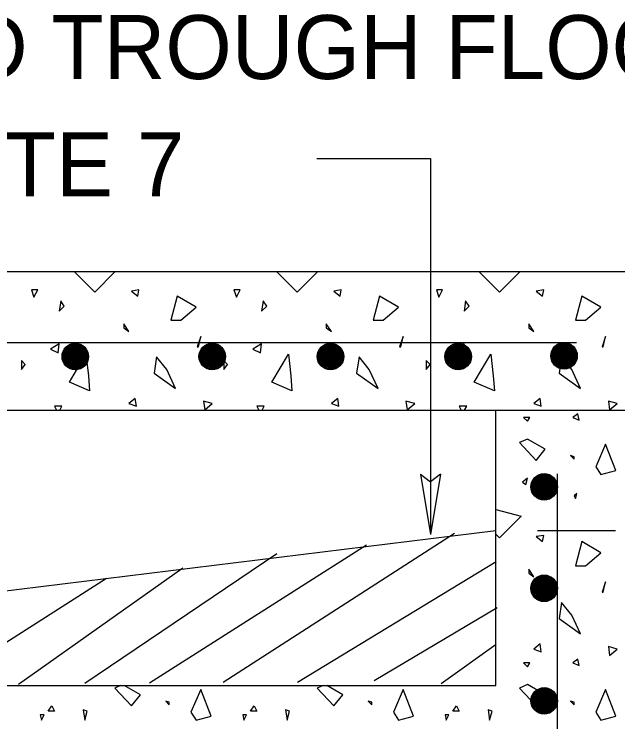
# Model space of a CAD drawing. Extents: x 5.8 to 18, y -5.2 to 5.4.
# Drawn here: x 8.074 to 8.641, y -0.237 to 0.427 of the extents above; entities that cross this region are included whole.
import ezdxf

# ---------------------------------------------------------------- set-up
doc = ezdxf.new("R2010")
doc.units = 0
for name, color, linetype in [('DETL-DIMS', 7, 'Continuous'), ('DETL-LINE', 7, 'Continuous'), ('DETL-NOTE', 7, 'Continuous'), ('DETL-PATT', 7, 'Continuous')]:
    doc.layers.add(name, color=color, linetype=linetype)

msp = doc.modelspace()

# ---------------------------------------------------------------- linework, layer by layer
at = {"layer": 'DETL-DIMS'}
for p, q in [((8.35804, 0.29176), (8.46478, 0.29176)), ((8.46478, 0.29176), (8.46478, -0.06106)), ((8.45537, -0.00459), (8.46478, -0.06106)), ((8.45537, -0.00459), (8.46478, -0.01165)), ((8.4742, -0.00459), (8.46478, -0.06106)), ((8.4742, -0.00459), (8.46478, -0.01165)), ((8.56541, -0.05742), (8.63843, -0.05742))]:
    msp.add_line(p, q, dxfattribs=at)
at = {"layer": 'DETL-LINE'}
for p, q in [((6.26486, 0.18564), (8.65804, 0.18564)), ((7.74588, 0.11902), (8.60188, 0.11902)), ((6.26243, 0.05545), (8.65804, 0.05545)), ((8.5262, -0.20279), (8.5262, 0.05545)), ((8.58404, -0.24561), (8.58404, -0.00424)), ((7.73561, -0.15436), (8.5262, -0.05742)), ((6.404, -0.20279), (8.5262, -0.20279))]:
    msp.add_line(p, q, dxfattribs=at)
for centre, radius in [((8.13138, 0.10591), 0.01247), ((8.13127, 0.10602), 0.01163), ((8.13016, 0.10602), 0.01009), ((8.13141, 0.10572), 0.01122), ((8.13175, 0.10519), 0.011), ((8.13169, 0.10558), 0.01024), ((8.13057, 0.10651), 0.00834), ((8.13196, 0.10552), 0.00969), ((8.13204, 0.10525), 0.00918), ((8.13218, 0.10511), 0.00876), ((8.13204, 0.1049), 0.00835), ((8.13225, 0.1049), 0.00814), ((8.25997, 0.10591), 0.01247), ((8.25986, 0.10602), 0.01163), ((8.25875, 0.10602), 0.01009), ((8.26, 0.10572), 0.01122), ((8.26033, 0.10519), 0.011), ((8.26027, 0.10558), 0.01024), ((8.25916, 0.10651), 0.00834), ((8.26055, 0.10552), 0.00969), ((8.26063, 0.10525), 0.00918), ((8.26076, 0.10511), 0.00876), ((8.26063, 0.1049), 0.00835), ((8.26084, 0.1049), 0.00814), ((8.37103, 0.10591), 0.01247), ((8.37092, 0.10602), 0.01163), ((8.3698, 0.10602), 0.01009), ((8.37106, 0.10572), 0.01122), ((8.37139, 0.10519), 0.011), ((8.37133, 0.10558), 0.01024), ((8.37022, 0.10651), 0.00834), ((8.37161, 0.10552), 0.00969), ((8.37169, 0.10525), 0.00918), ((8.37182, 0.10511), 0.00876), ((8.37169, 0.1049), 0.00835), ((8.3719, 0.1049), 0.00814), ((8.49083, 0.10591), 0.01247), ((8.49073, 0.10602), 0.01163), ((8.48961, 0.10602), 0.01009), ((8.49086, 0.10572), 0.01122), ((8.4912, 0.10519), 0.011), ((8.49114, 0.10558), 0.01024), ((8.49002, 0.10651), 0.00834), ((8.49141, 0.10552), 0.00969), ((8.49149, 0.10525), 0.00918), ((8.49163, 0.10511), 0.00876), ((8.49149, 0.1049), 0.00835), ((8.49171, 0.1049), 0.00814), ((8.5902, 0.10655), 0.01247), ((8.59009, 0.10665), 0.01163), ((8.58897, 0.10665), 0.01009), ((8.59023, 0.10636), 0.01122), ((8.59056, 0.10583), 0.011), ((8.5905, 0.10622), 0.01024), ((8.58938, 0.10714), 0.00834), ((8.59078, 0.10616), 0.00969), ((8.59085, 0.10589), 0.00918), ((8.58919, 0.10616), 0.00724), ((8.59099, 0.10575), 0.00876), ((8.59085, 0.10554), 0.00835), ((8.59107, 0.10554), 0.00814), ((8.59091, 0.10567), 0.00786), ((8.59127, 0.10548), 0.00751), ((8.13037, 0.10552), 0.00724), ((8.12975, 0.10511), 0.00578), ((8.1321, 0.10503), 0.00786), ((8.13245, 0.10484), 0.00751), ((8.13253, 0.10498), 0.00704), ((8.13071, 0.10539), 0.00467), ((8.13259, 0.10505), 0.00655), ((8.13259, 0.10519), 0.006), ((8.13267, 0.10503), 0.00565), ((8.13267, 0.10498), 0.0051), ((8.13288, 0.10454), 0.00488), ((8.133, 0.10449), 0.00445), ((8.133, 0.1046), 0.0039), ((8.13316, 0.1047), 0.00377), ((8.13316, 0.10435), 0.00347), ((8.13329, 0.10462), 0.00333), ((8.13335, 0.10454), 0.00285), ((8.13316, 0.10476), 0.00238), ((8.13343, 0.10447), 0.00212), ((8.25896, 0.10552), 0.00724), ((8.25833, 0.10511), 0.00578), ((8.26069, 0.10503), 0.00786), ((8.26104, 0.10484), 0.00751), ((8.26112, 0.10498), 0.00704), ((8.25929, 0.10539), 0.00467), ((8.26118, 0.10505), 0.00655), ((8.26118, 0.10519), 0.006), ((8.26125, 0.10503), 0.00565), ((8.26125, 0.10498), 0.0051), ((8.26147, 0.10454), 0.00488), ((8.26159, 0.10449), 0.00445), ((8.26159, 0.1046), 0.0039), ((8.26175, 0.1047), 0.00377), ((8.26175, 0.10435), 0.00347), ((8.26188, 0.10462), 0.00333), ((8.26194, 0.10454), 0.00285), ((8.26175, 0.10476), 0.00238), ((8.26202, 0.10447), 0.00212), ((8.37002, 0.10552), 0.00724), ((8.36939, 0.10511), 0.00578), ((8.37175, 0.10503), 0.00786), ((8.3721, 0.10484), 0.00751), ((8.37218, 0.10498), 0.00704), ((8.37035, 0.10539), 0.00467), ((8.37224, 0.10505), 0.00655), ((8.37224, 0.10519), 0.006), ((8.37231, 0.10503), 0.00565), ((8.37231, 0.10498), 0.0051), ((8.37253, 0.10454), 0.00488), ((8.37265, 0.10449), 0.00445), ((8.37265, 0.1046), 0.0039), ((8.3728, 0.1047), 0.00377), ((8.3728, 0.10435), 0.00347), ((8.37294, 0.10462), 0.00333), ((8.373, 0.10454), 0.00285), ((8.3728, 0.10476), 0.00238), ((8.37308, 0.10447), 0.00212), ((8.48982, 0.10552), 0.00724), ((8.4892, 0.10511), 0.00578), ((8.49155, 0.10503), 0.00786), ((8.4919, 0.10484), 0.00751), ((8.49198, 0.10498), 0.00704), ((8.49204, 0.10505), 0.00655), ((8.49016, 0.10539), 0.00467), ((8.49204, 0.10519), 0.006), ((8.49212, 0.10503), 0.00565), ((8.49212, 0.10498), 0.0051), ((8.49233, 0.10454), 0.00488), ((8.49245, 0.10449), 0.00445), ((8.49245, 0.1046), 0.0039), ((8.49261, 0.1047), 0.00377), ((8.49261, 0.10435), 0.00347), ((8.49275, 0.10462), 0.00333), ((8.4928, 0.10454), 0.00285), ((8.49261, 0.10476), 0.00238), ((8.49288, 0.10447), 0.00212), ((8.58856, 0.10575), 0.00578), ((8.59134, 0.10561), 0.00704), ((8.5914, 0.10569), 0.00655), ((8.58952, 0.10603), 0.00467), ((8.5914, 0.10583), 0.006), ((8.59148, 0.10567), 0.00565), ((8.59148, 0.10561), 0.0051), ((8.5917, 0.10518), 0.00488), ((8.59181, 0.10512), 0.00445), ((8.59181, 0.10524), 0.0039), ((8.59197, 0.10534), 0.00377), ((8.59197, 0.10499), 0.00347), ((8.59211, 0.10526), 0.00333), ((8.59217, 0.10518), 0.00285), ((8.59197, 0.1054), 0.00238), ((8.59225, 0.1051), 0.00212), ((8.59232, 0.10512), 0.00175), ((8.59246, 0.10505), 0.00133), ((8.59246, 0.10518), 0.00118), ((8.59287, 0.10512), 0.00148), ((8.13351, 0.10449), 0.00175), ((8.13365, 0.10441), 0.00133), ((8.13365, 0.10454), 0.00118), ((8.13406, 0.10449), 0.00148), ((8.13363, 0.10454), 0.000769), ((8.13349, 0.10454), 0.000362), ((8.13378, 0.10454), 0.00023), ((8.2621, 0.10449), 0.00175), ((8.26224, 0.10441), 0.00133), ((8.26224, 0.10454), 0.00118), ((8.26265, 0.10449), 0.00148), ((8.26222, 0.10454), 0.000769), ((8.26208, 0.10454), 0.000362), ((8.26237, 0.10454), 0.00023), ((8.37316, 0.10449), 0.00175), ((8.37329, 0.10441), 0.00133), ((8.37329, 0.10454), 0.00118), ((8.37371, 0.10449), 0.00148), ((8.37327, 0.10454), 0.000769), ((8.37314, 0.10454), 0.000362), ((8.37343, 0.10454), 0.00023), ((8.49296, 0.10449), 0.00175), ((8.4931, 0.10441), 0.00133), ((8.4931, 0.10454), 0.00118), ((8.49351, 0.10449), 0.00148), ((8.49308, 0.10454), 0.000769), ((8.49294, 0.10454), 0.000362), ((8.49324, 0.10454), 0.00023), ((8.59244, 0.10518), 0.000769), ((8.59231, 0.10518), 0.000362), ((8.5926, 0.10518), 0.00023), ((8.57157, -0.0164), 0.01247), ((8.57147, -0.01629), 0.01163), ((8.57035, -0.01629), 0.01009), ((8.5716, -0.01659), 0.01122), ((8.57194, -0.01712), 0.011), ((8.57188, -0.01672), 0.01024), ((8.57076, -0.0158), 0.00834), ((8.57215, -0.01678), 0.00969), ((8.57223, -0.01706), 0.00918), ((8.57056, -0.01678), 0.00724), ((8.57237, -0.01719), 0.00876), ((8.57223, -0.01741), 0.00835), ((8.56994, -0.01719), 0.00578), ((8.57245, -0.01741), 0.00814), ((8.57229, -0.01727), 0.00786), ((8.57264, -0.01747), 0.00751), ((8.57272, -0.01733), 0.00704), ((8.57278, -0.01725), 0.00655), ((8.5709, -0.01692), 0.00467), ((8.57278, -0.01712), 0.006), ((8.57286, -0.01727), 0.00565), ((8.57286, -0.01733), 0.0051), ((8.57307, -0.01776), 0.00488), ((8.57319, -0.01782), 0.00445), ((8.57319, -0.0177), 0.0039), ((8.57335, -0.01761), 0.00377), ((8.57335, -0.01796), 0.00347), ((8.57349, -0.01768), 0.00333), ((8.57355, -0.01776), 0.00285), ((8.57335, -0.01755), 0.00238), ((8.57362, -0.01784), 0.00212), ((8.5737, -0.01782), 0.00175), ((8.57384, -0.0179), 0.00133), ((8.57384, -0.01776), 0.00118), ((8.57425, -0.01782), 0.00148), ((8.57382, -0.01776), 0.000769), ((8.57368, -0.01776), 0.000362), ((8.57398, -0.01776), 0.00023), ((8.57156, -0.11162), 0.01247), ((8.57145, -0.11151), 0.01163), ((8.57033, -0.11151), 0.01009), ((8.57159, -0.11181), 0.01122), ((8.57192, -0.11234), 0.011), ((8.57186, -0.11194), 0.01024), ((8.57075, -0.11102), 0.00834), ((8.57214, -0.112), 0.00969), ((8.57222, -0.11228), 0.00918), ((8.57055, -0.112), 0.00724), ((8.57235, -0.11242), 0.00876), ((8.57222, -0.11263), 0.00835), ((8.57243, -0.11263), 0.00814), ((8.57227, -0.11249), 0.00786), ((8.57263, -0.11269), 0.00751), ((8.57271, -0.11255), 0.00704), ((8.57276, -0.11247), 0.00655), ((8.56992, -0.11242), 0.00578), ((8.57088, -0.11214), 0.00467), ((8.57276, -0.11234), 0.006), ((8.57284, -0.11249), 0.00565), ((8.57284, -0.11255), 0.0051), ((8.57306, -0.11298), 0.00488), ((8.57318, -0.11304), 0.00445), ((8.57318, -0.11293), 0.0039), ((8.57333, -0.11283), 0.00377), ((8.57333, -0.11318), 0.00347), ((8.57347, -0.11291), 0.00333), ((8.57353, -0.11298), 0.00285), ((8.57333, -0.11277), 0.00238), ((8.57361, -0.11306), 0.00212), ((8.57369, -0.11304), 0.00175), ((8.57382, -0.11312), 0.00133), ((8.57382, -0.11298), 0.00118), ((8.57424, -0.11304), 0.00148), ((8.5738, -0.11298), 0.000769), ((8.57367, -0.11298), 0.000362), ((8.57396, -0.11298), 0.00023), ((8.57157, -0.2173), 0.01247), ((8.57147, -0.21719), 0.01163), ((8.57035, -0.21719), 0.01009), ((8.5716, -0.21749), 0.01122), ((8.57194, -0.21802), 0.011), ((8.57188, -0.21763), 0.01024), ((8.57076, -0.2167), 0.00834), ((8.57215, -0.21768), 0.00969), ((8.57223, -0.21796), 0.00918), ((8.57056, -0.21768), 0.00724), ((8.57237, -0.2181), 0.00876), ((8.57223, -0.21831), 0.00835), ((8.56994, -0.2181), 0.00578), ((8.57245, -0.21831), 0.00814), ((8.57229, -0.21817), 0.00786), ((8.57264, -0.21837), 0.00751), ((8.57272, -0.21823), 0.00704), ((8.57278, -0.21815), 0.00655), ((8.57278, -0.21802), 0.006), ((8.57286, -0.21817), 0.00565), ((8.5709, -0.21782), 0.00467), ((8.57286, -0.21823), 0.0051), ((8.57307, -0.21866), 0.00488), ((8.57319, -0.21872), 0.00445), ((8.57319, -0.21861), 0.0039), ((8.57335, -0.21851), 0.00377), ((8.57335, -0.21886), 0.00347), ((8.57349, -0.21859), 0.00333), ((8.57355, -0.21866), 0.00285), ((8.57335, -0.21845), 0.00238), ((8.57362, -0.21874), 0.00212), ((8.5737, -0.21872), 0.00175), ((8.57384, -0.2188), 0.00133), ((8.57384, -0.21866), 0.00118), ((8.57425, -0.21872), 0.00148), ((8.57382, -0.21866), 0.000769), ((8.57368, -0.21866), 0.000362), ((8.57398, -0.21866), 0.00023)]:
    msp.add_circle(centre, radius, dxfattribs=at)
at = {"layer": 'DETL-PATT'}
for p, q in [((8.27012, -0.19961), (8.48753, -0.05977)), ((8.40475, -0.07098), (8.20106, -0.20055)), ((8.14043, -0.20063), (8.32063, -0.07891)), ((8.07796, -0.20161), (8.23224, -0.09248)), ((8.52635, -0.08687), (8.34012, -0.20004)), ((8.16075, -0.10236), (8.0089, -0.1993)), ((8.412, -0.19816), (8.52749, -0.12973)), ((8.47494, -0.20095), (8.52635, -0.16408))]:
    msp.add_line(p, q, dxfattribs=at)
for points in [[(8.16894, 0.18564), (8.14957, 0.16627), (8.13024, 0.18564)], [(8.35898, 0.18564), (8.33961, 0.16627), (8.32024, 0.18564)], [(8.54902, 0.18564), (8.52965, 0.16627), (8.51027, 0.18564)], [(8.11682, 0.05545), (8.11882, 0.05925), (8.11176, 0.05925), (8.11357, 0.05545)], [(8.30686, 0.05545), (8.30882, 0.05925), (8.30176, 0.05925), (8.30361, 0.05545)], [(8.49686, 0.05545), (8.49886, 0.05925), (8.4918, 0.05925), (8.49365, 0.05545)], [(8.5262, -0.03769), (8.54996, -0.04381), (8.52965, -0.06412), (8.5262, -0.06071)], [(8.17396, -0.20279), (8.16851, -0.2053), (8.18404, -0.22197), (8.19251, -0.21153), (8.17737, -0.20279)], [(8.364, -0.20279), (8.35851, -0.2053), (8.37404, -0.22197), (8.38251, -0.21153), (8.36737, -0.20279)]]:
    msp.add_lwpolyline(points, dxfattribs=at)
for points in [[(8.09027, 0.16854), (8.09255, 0.16149), (8.09624, 0.16854)], [(8.18404, 0.16741), (8.18996, 0.16258), (8.1911, 0.16854)], [(8.28031, 0.16854), (8.28259, 0.16149), (8.28624, 0.16854)], [(8.37404, 0.16741), (8.38, 0.16258), (8.3811, 0.16854)], [(8.47035, 0.16854), (8.47259, 0.16149), (8.47627, 0.16854)], [(8.56408, 0.16741), (8.57, 0.16258), (8.57114, 0.16854)], [(8.23035, 0.14), (8.24475, 0.15215), (8.22694, 0.16258), (8.22102, 0.14)], [(8.42035, 0.14), (8.43475, 0.15215), (8.41698, 0.16258), (8.41106, 0.14)], [(8.61039, 0.14), (8.62478, 0.15215), (8.60698, 0.16258), (8.60106, 0.14)], [(8.11769, 0.15807), (8.11627, 0.14847), (8.12106, 0.15329)], [(8.30769, 0.15807), (8.30627, 0.14847), (8.3111, 0.15329)], [(8.49773, 0.15807), (8.49631, 0.14847), (8.5011, 0.15329)], [(8.17698, 0.13662), (8.17698, 0.13294), (8.18176, 0.12956)], [(8.36698, 0.13662), (8.36698, 0.13294), (8.3718, 0.12956)], [(8.55702, 0.13662), (8.55702, 0.13294), (8.5618, 0.12956)], [(8.24588, 0.11517), (8.24698, 0.11517), (8.24925, 0.12478)], [(8.43588, 0.11517), (8.43702, 0.11517), (8.43929, 0.12478)], [(8.62592, 0.11517), (8.62706, 0.11517), (8.62929, 0.12478)], [(8.10808, 0.1129), (8.11514, 0.10925), (8.11627, 0.11772)], [(8.29812, 0.1129), (8.30518, 0.10925), (8.30627, 0.11772)], [(8.48812, 0.1129), (8.49518, 0.10925), (8.49631, 0.11772)], [(8.14365, 0.08776), (8.14478, 0.07364), (8.12588, 0.08184), (8.14141, 0.10811)], [(8.33369, 0.08776), (8.33482, 0.07364), (8.31588, 0.08184), (8.33141, 0.10811)], [(8.52369, 0.08776), (8.52482, 0.07364), (8.50592, 0.08184), (8.52145, 0.10811)], [(8.08071, 0.10219), (8.08071, 0.09372), (8.08435, 0.09851)], [(8.20776, 0.10556), (8.20549, 0.09031), (8.22553, 0.07592), (8.21733, 0.09372)], [(8.27071, 0.10219), (8.27071, 0.09372), (8.27439, 0.09851)], [(8.39776, 0.10556), (8.39553, 0.09031), (8.41557, 0.07592), (8.40737, 0.09372)], [(8.46075, 0.10219), (8.46075, 0.09372), (8.46439, 0.09851)], [(8.5878, 0.10556), (8.58553, 0.09031), (8.60557, 0.07592), (8.59741, 0.09372)], [(8.18769, 0.06658), (8.18176, 0.0618), (8.18882, 0.05925)], [(8.37773, 0.06658), (8.3718, 0.0618), (8.37886, 0.05925)], [(8.56776, 0.06658), (8.5618, 0.0618), (8.56886, 0.05925)], [(8.2518, 0.06407), (8.25294, 0.05588), (8.26, 0.0618)], [(8.4418, 0.06407), (8.44294, 0.05588), (8.45, 0.0618)], [(8.63184, 0.06407), (8.63298, 0.05588), (8.64004, 0.0618)], [(8.55224, 0.04882), (8.55588, 0.04513), (8.55816, 0.04882)], [(8.59851, 0.04882), (8.60447, 0.04627), (8.60333, 0.05219)], [(8.54855, 0.02509), (8.56408, 0.00843), (8.57255, 0.0189), (8.55588, 0.02847)], [(8.62478, -0.00483), (8.6389, -0.00118), (8.62929, 0.02368), (8.62, 0.00251)], [(8.59965, 0.01184), (8.59627, 0.01294), (8.59965, 0.00956)], [(8.5511, -0.01189), (8.55447, -0.01416), (8.55588, -0.00824)], [(8.6022, -0.02263), (8.59965, -0.02487), (8.60106, -0.02742)], [(8.56408, -0.06298), (8.57, -0.06781), (8.57114, -0.06189)], [(8.61039, -0.0904), (8.62478, -0.07824), (8.60698, -0.06781), (8.60106, -0.0904)], [(8.55702, -0.09377), (8.55702, -0.09746), (8.5618, -0.10083)], [(8.62592, -0.11522), (8.62706, -0.11522), (8.62929, -0.10565)], [(8.5878, -0.12483), (8.58553, -0.14008), (8.60557, -0.15448), (8.59741, -0.13671)], [(8.56776, -0.16381), (8.5618, -0.16859), (8.56886, -0.17114)], [(8.63184, -0.16636), (8.63298, -0.17451), (8.64004, -0.16859)], [(8.59851, -0.18157), (8.60447, -0.18412), (8.60333, -0.1782)], [(8.55224, -0.18157), (8.55588, -0.18526), (8.55816, -0.18157)], [(8.54855, -0.2053), (8.56408, -0.22197), (8.57255, -0.21153), (8.55588, -0.20193)], [(8.24475, -0.23522), (8.25886, -0.23157), (8.24925, -0.20671), (8.23992, -0.22789)], [(8.43475, -0.23522), (8.44886, -0.23157), (8.43929, -0.20671), (8.42996, -0.22789)], [(8.62478, -0.23522), (8.6389, -0.23157), (8.62929, -0.20671), (8.62, -0.22789)], [(8.21961, -0.21859), (8.21624, -0.21746), (8.21961, -0.22083)], [(8.40965, -0.21859), (8.40624, -0.21746), (8.40965, -0.22083)], [(8.59965, -0.21859), (8.59627, -0.21746), (8.59965, -0.22083)], [(8.10922, -0.22197), (8.11176, -0.22675), (8.1058, -0.22675)], [(8.13886, -0.22565), (8.14027, -0.23522), (8.14251, -0.22675)], [(8.29922, -0.22197), (8.30176, -0.22675), (8.29584, -0.22675)], [(8.32886, -0.22565), (8.33027, -0.23522), (8.33255, -0.22675)], [(8.48925, -0.22197), (8.4918, -0.22675), (8.48588, -0.22675)], [(8.5189, -0.22565), (8.52031, -0.23522), (8.52259, -0.22675)], [(8.09847, -0.23044), (8.09961, -0.23522), (8.10216, -0.23044)], [(8.28851, -0.23044), (8.28965, -0.23522), (8.29216, -0.23044)], [(8.47851, -0.23044), (8.47965, -0.23522), (8.4822, -0.23044)]]:
    msp.add_lwpolyline(points, close=True, dxfattribs=at)

# ---------------------------------------------------------------- texts
at = {"layer": 'DETL-NOTE'}
for s, p in [('SLOPED TROUGH FLOOR', (7.76114, 0.36635)), ('SEE NOTE 7', (7.76114, 0.25635))]:
    msp.add_text(s, height=0.06, dxfattribs=at).set_placement(p)

doc.saveas('drawing.dxf')
